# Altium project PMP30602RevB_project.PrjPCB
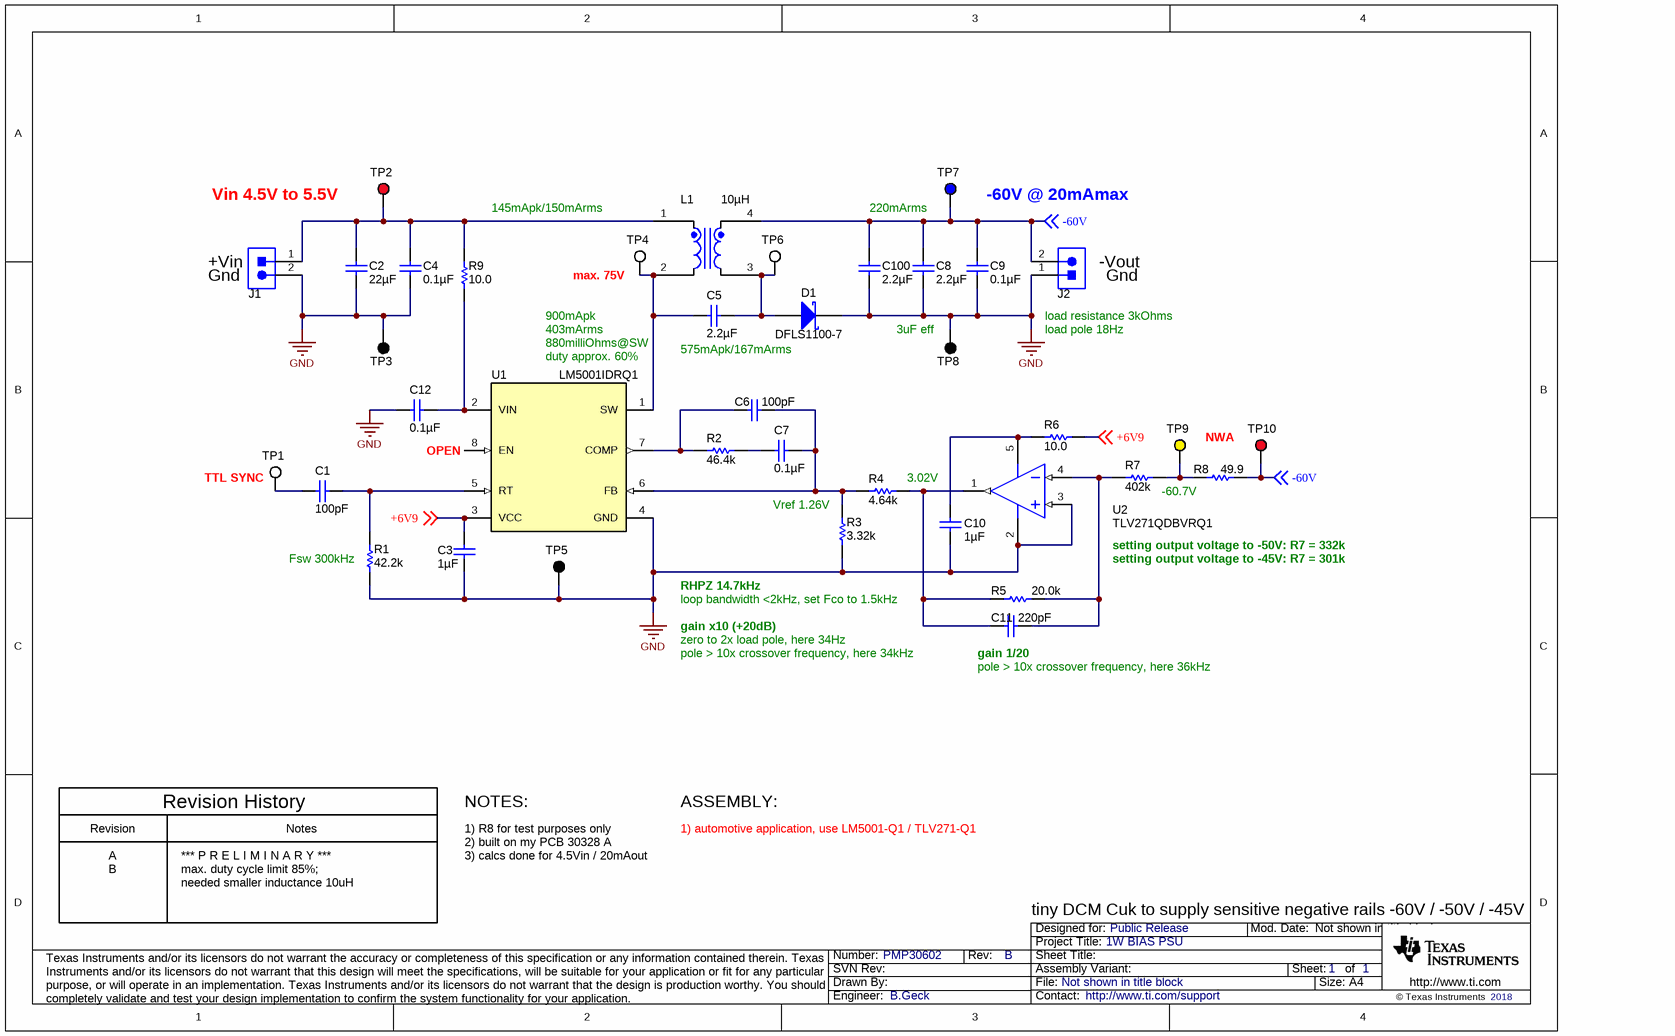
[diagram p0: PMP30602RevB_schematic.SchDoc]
CopyrightYear: 2018; PCB_Layout: B.Geck; PCB_Rev: A; PRJ_Customer: Public Release; PRJ_Engineer: B.Geck; PRJ_Number: PMP30602; PRJ_Title: 1W BIAS PSU; SCH_Rev: B; TechSupport: http://www.ti.com/support
1 sheet, 38 parts. Net scope: global (net labels, ports and power ports of the same name join across sheets).

## Sheet PMP30602RevB_schematic.SchDoc
size A4; Date: Not shown in title block; ApprovedBy: Not shown in title block; CheckedBy: Not shown in title block; Author: Not shown in title block; CompanyName: Not shown in title block; Engineer: Not shown in title block; Organization: Not shown in title block; Address1: Not shown in title block; Address2: Not shown in title block; Address3: Not shown in title block; Address4: Not shown in title block; DocumentNumber: 1; Revision: Use project parameter SCH_Rev; SheetNumber: 1; SheetTotal: 1; PageSetup: Record=PageOptions¦CenterHorizontal=True¦CenterVertical=True¦PrintScale=0.70¦XCorrection=1.00¦YCorrection=1.00¦PrintKind=0¦BorderSize=5000000¦LeftOffset=0¦BottomOffset=0¦Orientation=2¦PaperLength=1000¦PaperWidth=1000¦Scale=100¦PaperSource=15¦PrintQuality=600¦MediaType=1¦DitherType=10¦PaperKind=A4¦PrintScaleMode=1

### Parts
C1  ValueDisplayed: 100pF  [0603]  (hidden comment: GRM1885C1H101JA01D)
C2  ValueDisplayed: 22µF  [1206_180]  (hidden comment: GCM31CR71A226KE02)
C3  ValueDisplayed: 1µF  [0603]  (hidden comment: GRM188R71E105KA12D)
C4  ValueDisplayed: 0.1µF  [0603]  (hidden comment: GRM188R71E104KA01D)
C5  ValueDisplayed: 2.2µF  [1206_190]  (hidden comment: GRM31CR72A225KA73L)
C6  ValueDisplayed: 100pF  [0603]  (hidden comment: GRM1885C1H101JA01D)
C7  ValueDisplayed: 0.1µF  [0603]  (hidden comment: GRM188R71E104KA01D)
C8  ValueDisplayed: 2.2µF  [1206_190]  (hidden comment: GRM31CR72A225KA73L)
C9  ValueDisplayed: 0.1µF  [0603]  (hidden comment: GRM188R72A104KA35D)
C10  ValueDisplayed: 1µF  [0603]  (hidden comment: GRM188R71E105KA12D)
C11  ValueDisplayed: 220pF  [0603]  (hidden comment: GRM188R71H221KA01D)
C12  ValueDisplayed: 0.1µF  [0603]  (hidden comment: GRM188R71E104KA01D)
C100  ValueDisplayed: 2.2µF  [1206_190]  (hidden comment: GRM31CR72A225KA73L)
D1  DFLS1100-7  [PowerDI123]
J1  ED555/2DS  [TERM_BLK_ED555-2DS]  (value not drawn)
J2  ED555/2DS  [TERM_BLK_ED555-2DS]  (value not drawn)
L1  ValueDisplayed: 10µH  [IND_LPD5030]  (hidden comment: LPD5030-103MRB)
R1  ValueDisplayed: 42.2k  [0603]  (hidden comment: CRCW060342K2FKEA)
R2  ValueDisplayed: 46.4k  [0603]  (hidden comment: CRCW060346K4FKEA)
R3  ValueDisplayed: 3.32k  [0603]  (hidden comment: CRCW06033K32FKEA)
R4  ValueDisplayed: 4.64k  [0603]  (hidden comment: CRCW06034K64FKEA)
R5  ValueDisplayed: 20.0k  [0603]  (hidden comment: CRCW060320K0FKEA)
R6  ValueDisplayed: 10.0  [0603]  (hidden comment: CRCW060310R0FKEA)
R7  ValueDisplayed: 402k  [0603]  (hidden comment: CRCW0603402KFKEA)
R8  ValueDisplayed: 49.9  [0603]  (hidden comment: CRCW060349R9FKEA)
R9  ValueDisplayed: 10.0  [0603]  (hidden comment: CRCW060310R0FKEA)
TP1  5002  [Keystone5002]  (value not drawn)
TP2  5000  [Keystone5000]  (value not drawn)
TP3  5001  [Keystone5001]  (value not drawn)
TP4  5002  [Keystone5002]  (value not drawn)
TP5  5001  [Keystone5001]  (value not drawn)
TP6  5002  [Keystone5002]  (value not drawn)
TP7  5117  [Keystone5117]  (value not drawn)
TP8  5001  [Keystone5001]  (value not drawn)
TP9  5004  [Keystone5004]  (value not drawn)
TP10  5000  [Keystone5000]  (value not drawn)
U1  LM5001IDRQ1  [D0008A_N]
U2  TLV271QDBVRQ1  [DBV0005A_N]

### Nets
GND: C2.2 C3.2 C4.2 C8.2 C9.2 C10.2 C12.1 C100.2 D1.1(K) J1.2 J2.1 R1.2 R3.1 TP3.1 TP5.1 TP8.1 U1.4(GND) U2.2(GND) U2.3(IN+)
+6V9: C3.1 R6.2 U1.3(VCC) ; off-sheet +6V9
-60V: C8.1 C9.1 C100.1 J2.2 L1.4 R8.2 TP7.1 TP10.1 ; off-sheet -60V
NetC1_1: C1.1 R1.1 U1.5(RT)
NetC1_2: C1.2 TP1.1
NetC2_1: C2.1 C4.1 J1.1 L1.1 R9.2 TP2.1
NetC5_1: C5.1 L1.2 TP4.1 U1.1(SW)
NetC5_2: C5.2 D1.2(A) L1.3 TP6.1
NetC6_1: C6.1 C7.2 R3.2 R4.1 U1.6(FB)
NetC6_2: C6.2 R2.1 U1.7(COMP)
NetC7_1: C7.1 R2.2
NetC10_1: C10.1 R6.1 U2.5(VDD)
NetC11_1: C11.1 R5.2 R7.1 U2.4(IN-)
NetC11_2: C11.2 R4.2 R5.1 U2.1(OUT)
NetC12_2: C12.2 R9.1 U1.2(VIN)
NetR7_2: R7.2 R8.1 TP9.1

Not connected (* = marked no-connect by the designer): U1 8(EN)

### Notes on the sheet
- Vin 4.5V to 5.5V
- 145mApk/150mArms
- 220mArms
- -60V @ 20mAmax
- (near J1) +Vin
- (near J1) Gnd
- 900mApk
- (near TP4) max. 75V
- (near J2) load resistance 3kOhms
- (near J2) -Vout
- (near J2) Gnd
- 880milliOhms@SW
- 403mArms
- duty approx. 60%
- 575mApk/167mArms
- (near TP8) 3uF eff
- (near J2) load pole 18Hz
- OPEN
- NWA
- (near TP1) TTL SYNC
- (near R3) Vref 1.26V
- (near R4) 3.02V
- -60.7V
- (near R1) Fsw 300kHz
- RHPZ 14.7kHz
- setting output voltage to -50V: R7 = 332k
- setting output voltage to -45V: R7 = 301k
- gain x10 (+20dB)
- zero to 2x load pole, here 34Hz
- pole > 10x crossover frequency, here 34kHz
- loop bandwidth <2kHz, set Fco to 1.5kHz
- (near C11) gain 1/20
- (near C11) pole > 10x crossover frequency, here 36kHz
- Revision
- A
- *** P R E L I M I N A R Y ***
- Revision History
- Notes
- NOTES:
- 1) R8 for test purposes only
- 2) built on my PCB 30328 A
- 3) calcs done for 4.5Vin / 20mAout
- ASSEMBLY:
- 1) automotive application, use LM5001-Q1 / TLV271-Q1
- B
- max. duty cycle limit 85%;
- needed smaller inductance 10uH
- tiny DCM Cuk to supply sensitive negative rails -60V / -50V / -45V

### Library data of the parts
C1 = GRM1885C1H101JA01D: CAP, CERM, 100 pF, 50 V,+/- 5%, C0G/NP0, 0603; Manufacturer: MuRata; Polarized: N; CompType: Capacitor; Value: 100pF; U/M: EA; Cap_F: 0.0000000001; Tolerance_%: 5; Value1: Unknown; VDC_V: 50; Value2: 50V; TaMin_C: -55; TaMax_C: 125; SizeArea_mm2: 1.28; SizeAreaWB_mm2: 4.68; SizeX_mm: 1.6; SizeY_mm: 0.8; SizeZ_mm: 1; AEC Category: Q200; Green_Lifecycle: Active; Green_REACh: Passed
C2 = GCM31CR71A226KE02: CAP, CERM, 22 µF, 10 V,+/- 10%, X7R, AEC-Q200 Grade 1, 1206; Manufacturer: MuRata; Polarized: N; CompType: Capacitor; Value: 22uF; U/M: EA; Cap_F: 0.000022; Tolerance_%: 10; Value2: 10V; TaMin_C: -55; TaMax_C: 125; Cap_Case: 1206; SizeArea_mm2: 5.12; SizeAreaWB_mm2: 10.92; SizeX_mm: 3.2; SizeY_mm: 1.6; SizeZ_mm: 1.8; AEC Category: Q200; AEC Qualified: Y; AEC Grade: 1
C3 C10 = GRM188R71E105KA12D: CAP, CERM, 1 µF, 25 V,+/- 10%, X7R, 0603; Manufacturer: MuRata; Polarized: N; CompType: Capacitor; Value: 1uF; U/M: EA; Cap_F: 0.000001; Tolerance_%: 10; Value1: Unknown; VDC_V: 25; Value2: 25V; TaMin_C: -55; TaMax_C: 125; SizeArea_mm2: 1.28; SizeAreaWB_mm2: 4.68; SizeX_mm: 1.6; SizeY_mm: 0.8; SizeZ_mm: 1; AEC Category: Q200; Green_Lifecycle: Active; Green_REACh: Passed
C4 C7 C12 = GRM188R71E104KA01D: CAP, CERM, 0.1 µF, 25 V,+/- 10%, X7R, 0603; Manufacturer: MuRata; Polarized: N; CompType: Capacitor; Value: 0.1uF; U/M: EA; Cap_F: 0.0000001; Tolerance_%: 10; VDC_V: 25; Value2: 25V; TaMin_C: -55; TaMax_C: 125; SizeArea_mm2: 1.28; SizeAreaWB_mm2: 4.68; SizeX_mm: 1.6; SizeY_mm: 0.8; SizeZ_mm: 1; AEC Category: Q200; Green_Lifecycle: Active; Green_REACh: Passed
C5 C8 C100 = GRM31CR72A225KA73L: CAP, CERM, 2.2 µF, 100 V,+/- 10%, X7R, 1206; Manufacturer: MuRata; Polarized: N; CompType: Capacitor; Value: 2.2uF; U/M: EA; Cap_F: 0.0000022; Tolerance_%: 10; Value1: Unknown; VDC_V: 100; Value2: 100V; TaMin_C: -55; TaMax_C: 125; Cap_Case: 1206; SizeArea_mm2: 5.12; SizeAreaWB_mm2: 10.92; SizeX_mm: 3.2; SizeY_mm: 1.6; SizeZ_mm: 1.9; AEC Category: Q200; Green_Lifecycle: Active; Green_REACh: Passed
C6 = GRM1885C1H101JA01D: CAP, CERM, 100 pF, 50 V,+/- 5%, C0G/NP0, 0603; Manufacturer: MuRata; Polarized: N; CompType: Capacitor; Value: 100pF; U/M: EA; Cap_F: 0.0000000001; Tolerance_%: 5; VDC_V: 50; Value2: 50V; TaMin_C: -55; TaMax_C: 125; SizeArea_mm2: 1.28; SizeAreaWB_mm2: 4.68; SizeX_mm: 1.6; SizeY_mm: 0.8; SizeZ_mm: 1; AEC Category: Q200; Green_Lifecycle: Active; Green_REACh: Passed
C9 = GRM188R72A104KA35D: CAP, CERM, 0.1 µF, 100 V,+/- 10%, X7R, 0603; Manufacturer: MuRata; Polarized: N; CompType: Capacitor; Value: 0.1uF; U/M: EA; Cap_F: 0.0000001; Tolerance_%: 10; Value1: Unknown; VDC_V: 100; Value2: 100V; TaMin_C: -55; TaMax_C: 125; SizeArea_mm2: 1.28; SizeAreaWB_mm2: 4.68; SizeX_mm: 1.6; SizeY_mm: 0.8; SizeZ_mm: 1; AEC Category: Q200; Green_Lifecycle: Active; Green_REACh: Passed
C11 = GRM188R71H221KA01D: CAP, CERM, 220 pF, 50 V,+/- 10%, X7R, 0603; Manufacturer: MuRata; Polarized: N; CompType: Capacitor; Value: 220pF; U/M: EA; Cap_F: 0.00000000022; Tolerance_%: 10; VDC_V: 50; Value2: 50V; TaMin_C: -55; TaMax_C: 125; SizeArea_mm2: 1.28; SizeAreaWB_mm2: 4.68; SizeX_mm: 1.6; SizeY_mm: 0.8; SizeZ_mm: 1; AEC Category: Q200; Green_Lifecycle: Active; Green_REACh: Passed
D1 = DFLS1100-7: Diode, Schottky, 100 V, 1 A, PowerDI123; Manufacturer: Diodes Inc.; U/M: EA; Vf_V: 0.77; Value: 100V; Value1: 1A; Value2: 0.77V; Io_A: 1; Vr_V: 100; TJmax_C: 175; RJC_CperW: 7; SizeAreaWB_mm2: 13.066; SizeArea_mm2: 6.586; SizeX_mm: 3.7; SizeY_mm: 1.78; SizeZ_mm: 0.98; AEC Category: Q101; Green_Lifecycle: Active; Green_REACh: Passed
J1 J2 = ED555/2DS: Terminal Block, 6A, 3.5mm Pitch, 2-Pos, TH; Manufacturer: On-Shore Technology; SymbolCreator: a0412235; CompType: Connector; U/M: EA
L1 = LPD5030-103MRB: Coupled inductor, 10 µH, 1.2 A, 0.21 ohm, SMD; Manufacturer: Coilcraft; SymbolCreator: a0412235; Value: 10uH; Ind_H: 10.0E-6; DCR_ohm: 0.21; AEC Category: Q200; AEC Qualified: N
R1 = CRCW060342K2FKEA: RES, 42.2 k, 1%, 0.1 W, 0603; Manufacturer: Vishay-Dale; CompType: Resistor; Value: 42.2k; Res_ohm: 42200; Value_Code: 42k2; Tolerance_%: 1; Power_W: 0.1; Value2: 0.1W; VDC_V: 75; TempCo: 100 ppm/C; SizeArea_mm2: 1.28; SizeX_mm: 1.6; SizeY_mm: 0.8; EIA_Code: E96; U/M: EA; AEC Category: Q200; Green_Lifecycle: Active; Green_REACh: Passed
R2 = CRCW060346K4FKEA: RES, 46.4 k, 1%, 0.1 W, 0603; Manufacturer: Vishay-Dale; CompType: Resistor; Value: 46.4k; Res_ohm: 46400; Value_Code: 46k4; Tolerance_%: 1; Power_W: 0.1; Value2: 0.1W; VDC_V: 75; TempCo: 100 ppm/C; SizeArea_mm2: 1.28; SizeX_mm: 1.6; SizeY_mm: 0.8; EIA_Code: E96; U/M: EA; AEC Category: Q200; Green_Lifecycle: Active; Green_REACh: Passed
R3 = CRCW06033K32FKEA: RES, 3.32 k, 1%, 0.1 W, 0603; Manufacturer: Vishay-Dale; CompType: Resistor; Value: 3.32k; Res_ohm: 3320; Value_Code: 3k32; Tolerance_%: 1; Power_W: 0.1; Value2: 0.1W; VDC_V: 75; TempCo: 100 ppm/C; SizeArea_mm2: 1.28; SizeX_mm: 1.6; SizeY_mm: 0.8; EIA_Code: E96; U/M: EA; AEC Category: Q200; Green_Lifecycle: Active; Green_REACh: Passed
R4 = CRCW06034K64FKEA: RES, 4.64 k, 1%, 0.1 W, 0603; Manufacturer: Vishay-Dale; CompType: Resistor; Value: 4.64k; Res_ohm: 4640; Value_Code: 4k64; Tolerance_%: 1; Power_W: 0.1; Value2: 0.1W; VDC_V: 75; TempCo: 100 ppm/C; SizeArea_mm2: 1.28; SizeX_mm: 1.6; SizeY_mm: 0.8; EIA_Code: E96; U/M: EA; AEC Category: Q200; Green_Lifecycle: Active; Green_REACh: Passed
R5 = CRCW060320K0FKEA: RES, 20.0 k, 1%, 0.1 W, 0603; Manufacturer: Vishay-Dale; CompType: Resistor; Value: 20.0k; Res_ohm: 20000; Value_Code: 20k0; Tolerance_%: 1; Power_W: 0.1; Value2: 0.1W; VDC_V: 75; TempCo: 100 ppm/C; SizeArea_mm2: 1.28; SizeX_mm: 1.6; SizeY_mm: 0.8; EIA_Code: E96; U/M: EA; AEC Category: Q200; Green_Lifecycle: Active; Green_REACh: Passed
R6 = CRCW060310R0FKEA: RES, 10.0, 1%, 0.1 W, 0603; Manufacturer: Vishay-Dale; CompType: Resistor; Value: 10.0; Res_ohm: 10; Value_Code: 10R0; Tolerance_%: 1; Power_W: 0.1; Value2: 0.1W; VDC_V: 75; TempCo: 100 ppm/C; SizeArea_mm2: 1.28; SizeX_mm: 1.6; SizeY_mm: 0.8; EIA_Code: E96; U/M: EA; AEC Category: Q200; Green_Lifecycle: Active; Green_REACh: Passed
R7 = CRCW0603402KFKEA: RES, 402 k, 1%, 0.1 W, 0603; Manufacturer: Vishay-Dale; CompType: Resistor; Value: 402k; Res_ohm: 402000; Tolerance_%: 1; Power_W: 0.1; Value2: 0.1W; VDC_V: 75; TempCo: 100 ppm/C; SizeArea_mm2: 1.28; SizeX_mm: 1.6; SizeY_mm: 0.8; EIA_Code: E96; U/M: EA; AEC Category: Q200; Green_Lifecycle: Active; Green_REACh: Passed
R8 = CRCW060349R9FKEA: RES, 49.9, 1%, 0.1 W, 0603; Manufacturer: Vishay-Dale; CompType: Resistor; Value: 49.9; Value_Code: 49R9; Tolerance_%: 1; Power_W: 0.1; Value2: 0.1W; VDC_V: 75; TempCo: 100 ppm/C; SizeArea_mm2: 1.28; SizeX_mm: 1.6; SizeY_mm: 0.8; EIA_Code: E96; U/M: EA; AEC Category: Q200; Green_Lifecycle: Active; Green_REACh: Passed
R9 = CMP-0022003-2: RES, 10.0, 1%, 0.1 W, 0603; Manufacturer: Vishay-Dale; Power_W: 100mW; TempCo: 100 ppm/C; Value_Code: 10R0; U/M: EA; Value: 10.0; EIA_Code: E96; Res_ohm: 10; SizeX_mm: 1.6; SizeY_mm: 0.8; SizeZ_mm: 1; Value2: 0.1W; SizeArea_mm2: 1.28; CompType: Resistor; VDC_V: 75V; AEC Category: Q200
TP1 TP4 TP6 = 5002: Test Point, Miniature, White, TH; Manufacturer: Keystone; CompType: Test Point Loop; U/M: EA
TP2 TP10 = 5000: Test Point, Miniature, Red, TH; Manufacturer: Keystone; CompType: Test Point Loop; U/M: EA
TP3 TP5 TP8 = 5001: Test Point, Miniature, Black, TH; Manufacturer: Keystone; CompType: Test Point Loop; U/M: EA
TP7 = 5117: Test Point, Miniature, Blue, TH; Manufacturer: Keystone; CompType: Test Point Loop; U/M: EA; ContactFinish: Silver; Green_Lifecycle: Active; Green_REACh: Passed
TP9 = 5004: Test Point, Miniature, Yellow, TH; Manufacturer: Keystone; CompType: Test Point Loop; ContactFinish: Silver; Green_Lifecycle: Active; Green_REACh: Passed
U1 = LM5001IDRQ1: Automotive Grade 3.1-75V Wide Vin, 1A Current Mode Non-Synchronous Switch Mode Regulator, D0008A (SOIC-8); Manufacturer: Texas Instruments; SymbolCreator: a0411947; SizeArea_mm2: 30.38; SizeAreaWB_mm2: 56.58; SizeX_mm: 4.9; SizeY_mm: 6.2; SizeZ_mm: 1.75; CompType: IC; U/M: EA
U2 = TLV271QDBVRQ1: Automotive Catalog 550 uA/Ch, 3 MHz, Rail-to-Rail Output Operational Amplifier, 2.7 to 16 V, -40 to 125 degC, 5-pin SOT23 (DBV0005A), Green (RoHS & no Sb/Br); Manufacturer: Texas Instruments; Alternate PartNumber: Equivalent; CMRR(Min)(dB): 58; GBW(Typ)(MHz): 3; IIB(Max)(pA): 60; Iq per channel(Max)(mA): 0.66; Number of Channels: 1; Offset Drift(Typ)(uV/C): 2; Packing: LARGE T&R; Slew Rate(Typ)(V/us): 2.4; Sub Family: Low Supply Voltage Amplifier (<=2.7V), Precision Amplifier; Total Supply Voltage(Max)(+5V is 5, +/-5V is 10): 16; Total Supply Voltage(Min)(+5V is 5, +/-5V is 10): 2.7; Vio (25C)(Max)(mV): 5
